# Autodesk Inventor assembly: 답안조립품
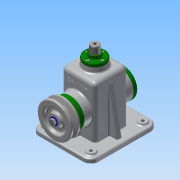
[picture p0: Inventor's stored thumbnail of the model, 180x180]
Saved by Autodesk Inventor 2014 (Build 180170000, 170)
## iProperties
Created: 2016-06
Part Number: 답안조립품
Document SubType Name: Assembly
Designer: Administrator
Author: Administrator
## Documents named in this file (19)
- C:\Users\Administrator\Desktop\ATC시험20160615\2016-0615Manufacturing2급\공용부품\답안조립품.iam
- C:\Users\Administrator\Desktop\ATC시험20160615\2016-0615Manufacturing2급\공용부품\1-본체.ipt
- C:\Users\Administrator\Desktop\ATC시험20160615\2016-0615Manufacturing2급\공용부품\V-벨트풀리.ipt
- C:\Users\Administrator\Desktop\ATC시험20160615\2016-0615Manufacturing2급\공용부품\고정핀.ipt
- C:\Users\Administrator\Desktop\ATC시험20160615\2016-0615Manufacturing2급\공용부품\뒤커버.ipt
- C:\Users\Administrator\Desktop\ATC시험20160615\2016-0615Manufacturing2급\공용부품\링크.ipt
- C:\Users\Administrator\Desktop\ATC시험20160615\2016-0615Manufacturing2급\공용부품\멈춤링 6 x 5.ipt
- C:\Users\Administrator\Desktop\ATC시험20160615\2016-0615Manufacturing2급\공용부품\멈춤링 15 x 1.ipt
- C:\Users\Administrator\Desktop\ATC시험20160615\2016-0615Manufacturing2급\공용부품\베어링 15 x 35 x 11.ipt
- C:\Users\Administrator\Desktop\ATC시험20160615\2016-0615Manufacturing2급\공용부품\볼트 M3 x 8.ipt
- C:\Users\Administrator\Desktop\ATC시험20160615\2016-0615Manufacturing2급\공용부품\볼트 M4 x 10.ipt
- C:\Users\Administrator\Desktop\ATC시험20160615\2016-0615Manufacturing2급\공용부품\볼트 M6 x 12.ipt
- C:\Users\Administrator\Desktop\ATC시험20160615\2016-0615Manufacturing2급\공용부품\상부부시.ipt
- C:\Users\Administrator\Desktop\ATC시험20160615\2016-0615Manufacturing2급\공용부품\슬라이드바.ipt
- C:\Users\Administrator\Desktop\ATC시험20160615\2016-0615Manufacturing2급\공용부품\앞커버.ipt
- C:\Users\Administrator\Desktop\ATC시험20160615\2016-0615Manufacturing2급\공용부품\오일실 15 25 7.ipt
- C:\Users\Administrator\Desktop\ATC시험20160615\2016-0615Manufacturing2급\공용부품\와셔.ipt
- C:\Users\Administrator\Desktop\ATC시험20160615\2016-0615Manufacturing2급\공용부품\키 5 x 5 x 14.ipt
- C:\Users\Administrator\Desktop\ATC시험20160615\2016-0615Manufacturing2급\공용부품\편심축.ipt
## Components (16 placed, 6 different names)
1. 1-본체:1
2. V-벨트풀리:1
3. 고정핀:1
4. ISO 4018 M6 x 12:1
5. ISO 4762 M4 x 10:2
6. ISO 4762 M4 x 10:3
7. ISO 4762 M4 x 10:4
8. ISO 4762 M4 x 10:5
9. ISO 4762 M4 x 10:1
10. ISO 4762 M4 x 10:6
11. ISO 4762 M4 x 10:7
12. ISO 4762 M4 x 10:8
13. ISO 4762 M3 x 8:1
14. ISO 4762 M3 x 8:2
15. ISO 4762 M3 x 8:3
16. ISO 4762 M3 x 8:4
